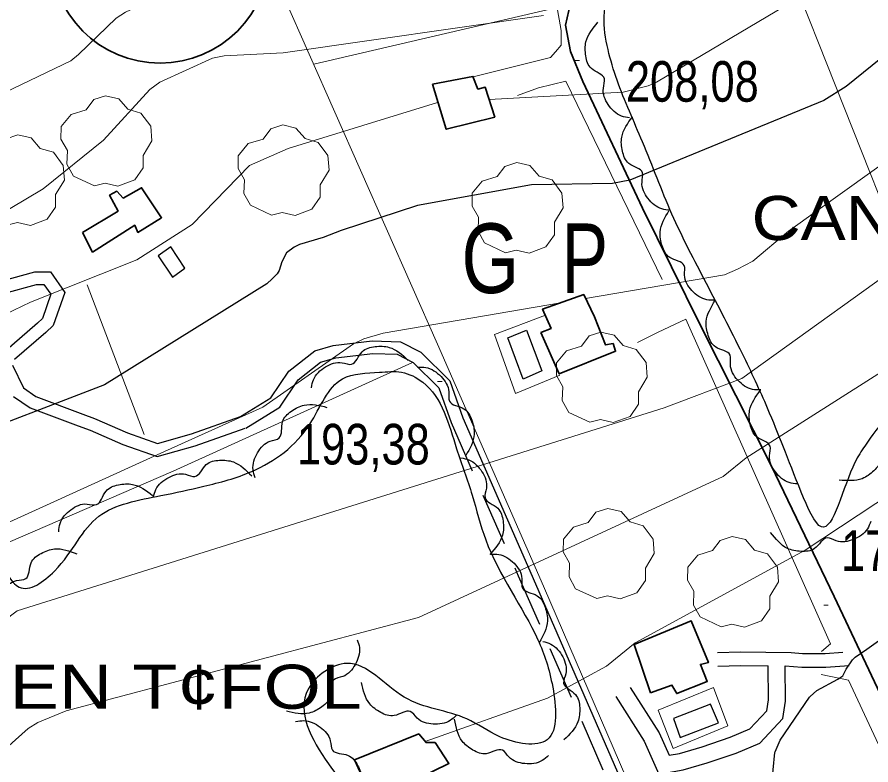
# Model space of a CAD drawing. Extents: x 483847 to 488453, y 4383581 to 4386795.
# Drawn here: x 485068.4 to 485252.4, y 4385313.2 to 4385474.4 of the extents above; entities that cross this region are included whole.
import ezdxf
from ezdxf.enums import TextEntityAlignment as Align

# ---------------------------------------------------------------- set-up
doc = ezdxf.new("R2010")
doc.units = 0
doc.header["$LTSCALE"] = 3.8
doc.linetypes.add('MEDIUM_DASHED', pattern=[4.5, 3, -1.5])
for name, color, linetype, lineweight in [('21', 7, 'Continuous', 25), ('27', 7, 'Continuous', 25), ('29', 7, 'Continuous', 13), ('38', 7, 'Continuous', 25), ('47', 7, 'Continuous', 35), ('51', 7, 'Continuous', 13), ('6', 7, 'Continuous', 35), ('7', 7, 'Continuous', 13), ('8', 7, 'Continuous', 25), ('9', 7, 'Continuous', 13)]:
    doc.layers.add(name, color=color, linetype=linetype, lineweight=lineweight)
doc.layers.add('31', color=7, linetype='Continuous')
doc.layers.add('5', color=7, linetype='Continuous')

msp = doc.modelspace()

# ---------------------------------------------------------------- linework, layer by layer
at = {"layer": '21'}
for points in [[(485098.8, 4385422.92), (485101.88, 4385418.32), (485104.57, 4385420.22), (485101.57, 4385424.87)], [(485178.15, 4385406.92), (485181.51, 4385398.11), (485177.48, 4385396.33), (485174.18, 4385405.25)], [(485211.28, 4385319.12), (485219.58, 4385322.31), (485217.81, 4385326.32), (485209.87, 4385323.23)]]:
    msp.add_lwpolyline(points, close=True, dxfattribs=at)
at = {"layer": '27'}
for points in [[(485299.82, 4385661.09), (485299.57, 4385662.67), (485294.64, 4385662.26), (485289.35, 4385654.61), (485280.21, 4385639.63), (485274.93, 4385631.94), (485268.4, 4385624.36), (485262.52, 4385617.77), (485260.31, 4385607.35), (485262.6, 4385605.35), (485273.48, 4385605.45), (485283.86, 4385606.12), (485288.68, 4385605.94), (485297.69, 4385606.01), (485307.73, 4385605.36), (485308.16, 4385598.4), (485301.92, 4385587.38), (485297.42, 4385582.21), (485286.33, 4385574.25), (485278.48, 4385567.13), (485277.89, 4385561.88), (485288.28, 4385555.36), (485288.05, 4385546.54), (485287.2, 4385540.29), (485287.59, 4385539.37), (485289.86, 4385531.35), (485293.31, 4385521.81), (485297.19, 4385508.56), (485300.77, 4385499.7), (485307.19, 4385485.75), (485313.31, 4385470.51), (485320.46, 4385455.75), (485325.62, 4385443.27), (485329.88, 4385435.24), (485331.55, 4385428.22), (485327.33, 4385421.28), (485318.2, 4385418.81), (485302.73, 4385416.83), (485290.31, 4385410.43), (485280.75, 4385407.62), (485276.69, 4385406.23), (485271.89, 4385402.9), (485261.87, 4385394.73), (485251.06, 4385381.93), (485248.95, 4385378.4), (485241.73, 4385364.5), (485237.39, 4385372.01), (485230.13, 4385390.06), (485224.7, 4385401.81), (485216.95, 4385416.96), (485209.52, 4385431.92), (485203.19, 4385447.45), (485197.7, 4385460.77), (485195.75, 4385467.38), (485194.93, 4385474.55), (485200.43, 4385487.01), (485210.67, 4385493.29), (485216.48, 4385500.54), (485216.66, 4385510.32), (485213.78, 4385515.61), (485201.98, 4385523.45), (485188.34, 4385524.69), (485179.71, 4385525), (485175.53, 4385527.17), (485167.01, 4385529.85), (485158.32, 4385525.02), (485150.05, 4385519.91), (485142.58, 4385519.6), (485127.69, 4385523.06), (485122.02, 4385531.44), (485127.14, 4385537.4), (485137.41, 4385536.78), (485149.71, 4385533.1), (485155.77, 4385534.88), (485159.76, 4385539.39), (485157.38, 4385543.53), (485170.25, 4385547.87), (485180.21, 4385553.72), (485186.2, 4385561.9), (485185.3, 4385569.26), (485178.59, 4385574.36), (485170, 4385578.4), (485148.21, 4385590.42), (485129.65, 4385601.13), (485118.26, 4385609.29), (485112.23, 4385612.98), (485102.9, 4385618.84), (485099.35, 4385621.2), (485098.35, 4385621.8), (485099.39, 4385628.01), (485103.9, 4385633.91)], [(485138.09, 4385491.7), (485117.52, 4385494.92), (485086.01, 4385503.28), (485081.51, 4385513.57), (485077.65, 4385527.72), (485084.73, 4385543.16), (485084.73, 4385555.38), (485066.08, 4385566.96), (485045.5, 4385568.25), (485042.29, 4385563.1), (485044.86, 4385545.73), (485048.08, 4385539.3), (485038.43, 4385530.3), (485026.22, 4385523.86), (485021.07, 4385512.28), (485022.36, 4385491.06), (485024.29, 4385447.96), (485003.07, 4385438.95), (484987.64, 4385455.68), (484988.92, 4385488.48), (484976.71, 4385515.5), (484956.13, 4385517.43), (484943.27, 4385480.76), (484939.42, 4385462.75), (484925.91, 4385453.1), (484916.27, 4385460.18), (484918.84, 4385487.84), (484918.2, 4385505.85), (484902.77, 4385501.35), (484880.26, 4385476.26), (484861.62, 4385445.39), (484883.48, 4385433.16), (484904.7, 4385434.45), (484917.56, 4385425.44), (484886.69, 4385394.57), (484833.97, 4385350.18), (484770.96, 4385312.88), (484729.17, 4385266.56), (484722.1, 4385262.06)], [(485200.39, 4385452.64), (485198.66, 4385453.01), (485195.79, 4385455.5), (485194.74, 4385459.03), (485194.98, 4385461.07), (485192.18, 4385463.26), (485190.96, 4385465.99), (485190.99, 4385469.01), (485193.58, 4385473.24)], [(485209.12, 4385432.74), (485207.36, 4385433), (485204.34, 4385435.3), (485203.07, 4385438.76), (485203.18, 4385440.81), (485200.24, 4385442.82), (485198.86, 4385445.47), (485198.7, 4385448.49), (485201.02, 4385452.87)], [(485218.82, 4385413.33), (485217.05, 4385413.43), (485213.83, 4385415.43), (485212.24, 4385418.76), (485212.16, 4385420.82), (485209.05, 4385422.54), (485207.42, 4385425.04), (485206.98, 4385428.03), (485208.87, 4385432.62)], [(485228.69, 4385394), (485226.91, 4385394.11), (485223.7, 4385396.13), (485222.12, 4385399.47), (485222.05, 4385401.52), (485218.95, 4385403.26), (485217.34, 4385405.77), (485216.91, 4385408.76), (485218.83, 4385413.33)], [(485131.82, 4385394.49), (485132.26, 4385396.21), (485134.87, 4385398.97), (485138.45, 4385399.87), (485140.47, 4385399.54), (485142.78, 4385402.25), (485145.56, 4385403.35), (485148.57, 4385403.19), (485152.69, 4385400.42)], [(485154.72, 4385398.91), (485156.49, 4385398.85), (485159.76, 4385396.92), (485161.43, 4385393.63), (485161.56, 4385391.58), (485164.71, 4385389.93), (485166.4, 4385387.47), (485166.91, 4385384.49), (485165.11, 4385379.86)], [(485052.44, 4385364.8), (485048.92, 4385362.19), (485040.02, 4385358.72), (485024.72, 4385354.86), (485017.53, 4385351.95), (485003.29, 4385349.24), (484982.72, 4385342.51), (484974.56, 4385332.02), (484981.15, 4385319.05), (484982.31, 4385313.35), (484982.65, 4385294.37), (484983.39, 4385269.53), (484987.68, 4385251.41), (484996.81, 4385238.57), (485031.48, 4385237.2), (485037.8, 4385239.34), (485054.61, 4385248.35), (485064.38, 4385252.89), (485078.44, 4385258.07), (485096.56, 4385262.47), (485096.84, 4385262.77), (485103.74, 4385262.86), (485111.59, 4385265.05), (485112.39, 4385270.45), (485114.5, 4385279.23), (485120.51, 4385283.33), (485139.84, 4385291), (485153.97, 4385297.17), (485158.64, 4385300.35), (485154.47, 4385304.25), (485147.71, 4385304.01), (485135.53, 4385313.41), (485131.15, 4385329.54), (485139.45, 4385335.08), (485151.84, 4385327.8), (485165.34, 4385323.12), (485172.43, 4385319.28), (485182.63, 4385318.65), (485183.82, 4385329.99), (485180.64, 4385340.15), (485169.39, 4385361.72), (485166.47, 4385371.34), (485163.13, 4385381.35), (485155.81, 4385395.69), (485151.26, 4385397.82), (485146.5, 4385397.81), (485138.56, 4385396.41), (485131.49, 4385386.65), (485118.99, 4385376.45), (485108.62, 4385373.24), (485099.38, 4385371.24), (485086.02, 4385366.81), (485076.47, 4385354.99), (485068.85, 4385351.52), (485066.46, 4385354.04), (485060, 4385363.04), (485052.44, 4385364.8)], [(485236.57, 4385373.76), (485234.81, 4385374.04), (485231.81, 4385376.36), (485230.56, 4385379.83), (485230.68, 4385381.88), (485227.76, 4385383.91), (485226.39, 4385386.56), (485226.26, 4385389.58), (485228.6, 4385393.95)], [(485258.54, 4385391.99), (485259.23, 4385390.35), (485258.84, 4385386.58), (485256.55, 4385383.68), (485254.74, 4385382.71), (485254.56, 4385379.16), (485253.02, 4385376.6), (485250.53, 4385374.89), (485245.58, 4385374.58)], [(485119.68, 4385375.09), (485119.25, 4385376.81), (485120.23, 4385380.48), (485122.94, 4385382.98), (485124.88, 4385383.66), (485125.61, 4385387.14), (485127.53, 4385389.43), (485130.26, 4385390.73), (485135.19, 4385390.26)], [(485097.75, 4385370.88), (485098.31, 4385372.56), (485101.08, 4385375.15), (485104.71, 4385375.83), (485106.71, 4385375.37), (485109.18, 4385377.93), (485112.02, 4385378.85), (485115.02, 4385378.5), (485118.96, 4385375.48)], [(485164.06, 4385379.36), (485165.78, 4385378.94), (485168.58, 4385376.38), (485169.54, 4385372.81), (485169.24, 4385370.78), (485171.98, 4385368.51), (485173.12, 4385365.75), (485173.01, 4385362.73), (485170.3, 4385358.58)], [(485077.38, 4385363.46), (485077.67, 4385365.22), (485080, 4385368.2), (485083.49, 4385369.43), (485085.53, 4385369.29), (485087.58, 4385372.2), (485090.24, 4385373.55), (485093.27, 4385373.67), (485097.62, 4385371.29)], [(485252.36, 4385365.69), (485251.64, 4385364.07), (485248.61, 4385361.78), (485244.93, 4385361.48), (485242.99, 4385362.14), (485240.27, 4385359.85), (485237.35, 4385359.22), (485234.4, 4385359.87), (485230.79, 4385363.28)], [(485064.1, 4385345.48), (485063.88, 4385347.24), (485065.28, 4385350.76), (485068.28, 4385352.93), (485070.28, 4385353.37), (485071.43, 4385356.74), (485073.6, 4385358.79), (485076.46, 4385359.75), (485081.31, 4385358.7)], [(485170.44, 4385358.61), (485172.21, 4385358.56), (485175.49, 4385356.65), (485177.18, 4385353.36), (485177.31, 4385351.31), (485180.47, 4385349.68), (485182.17, 4385347.22), (485182.7, 4385344.25), (485180.93, 4385339.61)], [(485141.71, 4385340.19), (485142.17, 4385338.48), (485141.25, 4385334.8), (485138.57, 4385332.25), (485136.64, 4385331.54), (485135.96, 4385328.06), (485134.08, 4385325.74), (485131.37, 4385324.39), (485126.43, 4385324.79)], [(485181.73, 4385339.83), (485183.41, 4385339.26), (485185.99, 4385336.48), (485186.65, 4385332.85), (485186.18, 4385330.85), (485188.73, 4385328.36), (485189.64, 4385325.52), (485189.27, 4385322.52), (485186.23, 4385318.6)], [(485163.11, 4385323.93), (485161.76, 4385322.78), (485158.05, 4385322), (485154.6, 4385323.3), (485153.12, 4385324.73), (485149.68, 4385323.83), (485146.77, 4385324.51), (485144.39, 4385326.36), (485142.59, 4385330.99)], [(485182.93, 4385315.24), (485181.55, 4385314.13), (485177.81, 4385313.49), (485174.4, 4385314.92), (485172.98, 4385316.4), (485169.51, 4385315.63), (485166.63, 4385316.41), (485164.31, 4385318.36), (485162.69, 4385323.04)], [(485128.43, 4385322.53), (485130.19, 4385322.76), (485133.72, 4385321.38), (485135.9, 4385318.4), (485136.36, 4385316.4), (485139.73, 4385315.27), (485141.79, 4385313.11), (485142.78, 4385310.26), (485141.75, 4385305.4)]]:
    msp.add_spline(points, degree=3, dxfattribs=at)
at = {"layer": '29'}
for points in [[(485085.09, 4385437.99), (485080.55, 4385440.11), (485079.14, 4385442.65), (485079.24, 4385445.63), (485077.87, 4385448.04), (485077.91, 4385450.79), (485080.07, 4385453.39), (485083.26, 4385454.39), (485084.91, 4385456.58), (485087.48, 4385457.41), (485090.34, 4385456.76), (485092.29, 4385454.49), (485095.1, 4385453.67), (485097.23, 4385450.82), (485097.47, 4385447.69), (485095.59, 4385444.54), (485095.59, 4385441.86), (485093.77, 4385439.25), (485090.15, 4385437.91), (485087.38, 4385438.54)], [(485123.25, 4385431.68), (485118.71, 4385433.8), (485117.3, 4385436.34), (485117.4, 4385439.32), (485116.03, 4385441.73), (485116.07, 4385444.48), (485118.23, 4385447.08), (485121.42, 4385448.08), (485123.07, 4385450.27), (485125.64, 4385451.1), (485128.5, 4385450.45), (485130.45, 4385448.18), (485133.26, 4385447.36), (485135.39, 4385444.51), (485135.63, 4385441.38), (485133.75, 4385438.23), (485133.75, 4385435.55), (485131.93, 4385432.94), (485128.31, 4385431.6), (485125.54, 4385432.23)], [(485066.21, 4385429.54), (485061.67, 4385431.66), (485060.26, 4385434.2), (485060.36, 4385437.18), (485058.99, 4385439.59), (485059.03, 4385442.34), (485061.19, 4385444.94), (485064.38, 4385445.94), (485066.03, 4385448.13), (485068.6, 4385448.96), (485071.46, 4385448.31), (485073.41, 4385446.04), (485076.22, 4385445.22), (485078.35, 4385442.37), (485078.59, 4385439.24), (485076.71, 4385436.09), (485076.71, 4385433.41), (485074.89, 4385430.8), (485071.27, 4385429.46), (485068.5, 4385430.09)], [(485173.68, 4385423.58), (485169.14, 4385425.7), (485167.73, 4385428.24), (485167.83, 4385431.22), (485166.46, 4385433.63), (485166.5, 4385436.38), (485168.66, 4385438.98), (485171.85, 4385439.98), (485173.5, 4385442.17), (485176.07, 4385443), (485178.93, 4385442.35), (485180.88, 4385440.08), (485183.69, 4385439.26), (485185.82, 4385436.41), (485186.06, 4385433.28), (485184.18, 4385430.13), (485184.18, 4385427.45), (485182.36, 4385424.84), (485178.74, 4385423.5), (485175.97, 4385424.13)], [(485191.83, 4385387.06), (485187.29, 4385389.18), (485185.88, 4385391.72), (485185.98, 4385394.7), (485184.61, 4385397.11), (485184.65, 4385399.86), (485186.81, 4385402.46), (485190, 4385403.46), (485191.65, 4385405.65), (485194.22, 4385406.48), (485197.08, 4385405.83), (485199.03, 4385403.56), (485201.84, 4385402.74), (485203.97, 4385399.89), (485204.21, 4385396.76), (485202.33, 4385393.61), (485202.33, 4385390.93), (485200.51, 4385388.32), (485196.89, 4385386.98), (485194.12, 4385387.61)], [(485193.31, 4385349.06), (485188.77, 4385351.18), (485187.36, 4385353.72), (485187.46, 4385356.7), (485186.09, 4385359.11), (485186.13, 4385361.86), (485188.29, 4385364.46), (485191.48, 4385365.46), (485193.13, 4385367.65), (485195.7, 4385368.48), (485198.56, 4385367.83), (485200.51, 4385365.56), (485203.32, 4385364.74), (485205.45, 4385361.89), (485205.69, 4385358.76), (485203.81, 4385355.61), (485203.81, 4385352.93), (485201.99, 4385350.32), (485198.37, 4385348.98), (485195.6, 4385349.61)], [(485220.11, 4385342.99), (485215.57, 4385345.11), (485214.16, 4385347.65), (485214.26, 4385350.63), (485212.89, 4385353.04), (485212.93, 4385355.79), (485215.09, 4385358.39), (485218.28, 4385359.39), (485219.93, 4385361.58), (485222.5, 4385362.41), (485225.36, 4385361.76), (485227.31, 4385359.49), (485230.12, 4385358.67), (485232.25, 4385355.82), (485232.49, 4385352.69), (485230.61, 4385349.54), (485230.61, 4385346.86), (485228.79, 4385344.25), (485225.17, 4385342.91), (485222.4, 4385343.54)]]:
    msp.add_lwpolyline(points, close=True, dxfattribs=at)
at = {"layer": '38'}
for points in [[(485065.19, 4385417.49), (485072.25, 4385419.43), (485075.62, 4385419.44), (485078.69, 4385415.03), (485076.2, 4385407.88), (485074.63, 4385406.38), (485067.86, 4385400.55)], [(485067.39, 4385399.36), (485069.79, 4385394.43), (485072.48, 4385392.57), (485082.54, 4385388.78), (485085.12, 4385387.84), (485092.19, 4385384.78), (485098.68, 4385382.49), (485105.97, 4385384.57), (485116.53, 4385388.26), (485123.1, 4385392.33), (485126.98, 4385398.05), (485132.55, 4385402.45), (485136.54, 4385403.6), (485144.94, 4385404.58), (485151.01, 4385404.41), (485155.4, 4385402.14), (485161.67, 4385395.96), (485164.46, 4385388.01), (485178.88, 4385355.05), (485199.04, 4385308.83)], [(485219.31, 4385337.44), (485224.28, 4385337.58), (485235.23, 4385337.44), (485237.65, 4385337.25), (485242.56, 4385337.24), (485246.36, 4385337.51)], [(485197.46, 4385327.96), (485203.56, 4385318.36), (485206.72, 4385311.25), (485211.95, 4385312.14), (485217.14, 4385313.66), (485223.37, 4385315.76), (485228.43, 4385317.92), (485233.42, 4385323.18), (485234.01, 4385326.96), (485233.89, 4385334.57)], [(485200.54, 4385329.92), (485206.79, 4385320.09), (485208.9, 4385315.33), (485211.13, 4385315.7), (485216.04, 4385317.14), (485222.07, 4385319.17), (485226.3, 4385320.98), (485229.99, 4385324.87), (485230.35, 4385327.21), (485230.24, 4385334.54)], [(485219.39, 4385334.48), (485224.3, 4385334.62), (485230.24, 4385334.54)], [(485233.89, 4385334.57), (485237.53, 4385334.29), (485242.66, 4385334.28), (485247.71, 4385334.64)]]:
    msp.add_lwpolyline(points, dxfattribs=at)
at = {"layer": '38', "linetype": 'MEDIUM_DASHED'}
for points in [[(485065.77, 4385414.84), (485072.62, 4385416.72), (485074.2, 4385416.72), (485075.68, 4385414.62), (485073.85, 4385409.39), (485072.8, 4385408.39), (485065.59, 4385402.17)], [(485067.66, 4385392.6), (485071.21, 4385390.15), (485081.6, 4385386.24), (485084.12, 4385385.32), (485091.2, 4385382.25), (485098.59, 4385379.65), (485106.79, 4385381.98), (485117.7, 4385385.79), (485125.02, 4385390.33), (485128.99, 4385396.18), (485133.82, 4385399.99), (485137.08, 4385400.94), (485145.06, 4385401.86), (485150.31, 4385401.71), (485153.79, 4385399.92), (485159.32, 4385394.47), (485161.93, 4385387.02), (485176.4, 4385353.96), (485196.56, 4385307.73)]]:
    msp.add_lwpolyline(points, dxfattribs=at)
at = {"layer": '47'}
for points in [[(485157.91, 4385459.88), (485160.87, 4385450.17), (485171.35, 4385452.79), (485169.29, 4385459.24), (485167.71, 4385458.83), (485166.62, 4385461.56)], [(485082.53, 4385427.94), (485084.69, 4385423.7), (485093.76, 4385429.51), (485094.46, 4385427.94), (485099.56, 4385431.12), (485095.24, 4385437.59), (485091.29, 4385435.36), (485089.9, 4385436.83), (485088.33, 4385435.98), (485090.17, 4385432.56)], [(485181.27, 4385406.37), (485185.25, 4385397.47), (485197.39, 4385402.36), (485196.83, 4385404), (485195.21, 4385403.7), (485192.81, 4385409.78), (485190.5, 4385414.54), (485181.65, 4385411.45), (485183.49, 4385407.27)], [(485204.89, 4385328.76), (485201.35, 4385339.15), (485213.69, 4385344.25), (485217.37, 4385335.26), (485215.64, 4385334.88), (485217.12, 4385331.16), (485210.57, 4385328.57), (485209.5, 4385330.43)], [(485141.14, 4385314.33), (485145.12, 4385305.57), (485161.46, 4385313.55), (485158.47, 4385318.05), (485156.53, 4385318.03), (485154.97, 4385319.9)]]:
    msp.add_lwpolyline(points, close=True, dxfattribs=at)
at = {"layer": '51'}
for p, q in [((485184.77, 4385476.42), (485132.37, 4385464.18)), ((485095.77, 4385384.39), (485083.48, 4385416.69))]:
    msp.add_line(p, q, dxfattribs=at)
for points in [[(485339.37, 4385421.12), (485279.8, 4385375.88), (485259.62, 4385422.12), (485233.6, 4385487.71), (485220.71, 4385521.12)], [(485179.99, 4385489.18), (485180.55, 4385483.65), (485183.72, 4385481.9), (485184.64, 4385477.14), (485185.67, 4385471.49), (485185.65, 4385468.27), (485184.4, 4385466.9), (485183.33, 4385465.68), (485166.67, 4385461.46)], [(485285.53, 4385247.86), (485313.01, 4385192.5), (485313.42, 4385190.87), (485268.44, 4385152.71), (485257.99, 4385177.32), (485238.37, 4385220.27), (485217.56, 4385269.02), (485181.87, 4385351.76), (485159, 4385403.87), (485125.85, 4385478.91)], [(485207.45, 4385417.8), (485186.67, 4385460.58), (485180.78, 4385459.08), (485176.23, 4385457.47)], [(485185.34, 4385397.22), (485175.82, 4385393.26), (485171.26, 4385405.95), (485182.25, 4385410.09)], [(485241.72, 4385337.66), (485243.71, 4385339.31), (485212.54, 4385409.27), (485206.57, 4385406.45), (485202.08, 4385404.26)], [(485153.65, 4385399.89), (485102.04, 4385376.52), (485031.36, 4385345.95)], [(485280.64, 4385252.83), (485282.73, 4385255.99), (485247.58, 4385331.44), (485241.69, 4385332.71)]]:
    msp.add_lwpolyline(points, dxfattribs=at)
msp.add_lwpolyline([(485218.51, 4385329.88), (485221.53, 4385321.65), (485209.79, 4385316.72), (485206.56, 4385325)], close=True, dxfattribs=at)
at = {"layer": '6'}
msp.add_lwpolyline([(485255.01, 4385327.15), (485244.49, 4385349.47), (485230.92, 4385377.71), (485215.65, 4385407.92), (485203.16, 4385433.2), (485190.33, 4385460.5), (485187.63, 4385466.91), (485186.62, 4385472.64), (485187.63, 4385477.36)], dxfattribs=at)
msp.add_circle((485099.22, 4385487.99), 23.55, dxfattribs=at)
at = {"layer": '7'}
for p, q in [((485188.59, 4385464.98), (485189.59, 4385464.98)), ((485158.98, 4385395.83), (485159.98, 4385395.83)), ((485242.22, 4385347.62), (485243.22, 4385347.62))]:
    msp.add_line(p, q, dxfattribs=at)
at = {"layer": '8'}
for points in [[(485261.67, 4385471.15), (485247.08, 4385459.38), (485242.22, 4385456.39), (485200.45, 4385439.21), (485196.72, 4385438.49), (485179.29, 4385438.22), (485154.72, 4385433.77), (485138.23, 4385428.4), (485134.34, 4385426.84), (485129.23, 4385425.36), (485128.13, 4385424.78), (485126.48, 4385423.52), (485125.43, 4385421.58), (485124.9, 4385419.73), (485124.42, 4385419.03), (485123.38, 4385417.93), (485122.22, 4385416.91), (485087.22, 4385395.08), (485053.89, 4385382.33), (484777.81, 4385260.43)], [(485229.41, 4385304.35), (485230.48, 4385306.55), (485230.95, 4385308.33), (485231.36, 4385312.16), (485231.7, 4385315.91), (485231.74, 4385316.06), (485232.81, 4385318.56), (485239.18, 4385327.79), (485239.3, 4385327.94), (485240.77, 4385329.25), (485245.24, 4385331.67), (485246.36, 4385332.42), (485246.37, 4385332.43), (485246.39, 4385332.57), (485247.04, 4385333.85), (485248.43, 4385335.82), (485249.03, 4385336.42), (485251.55, 4385338.13), (485280.38, 4385358.8)]]:
    msp.add_lwpolyline(points, dxfattribs=at)
at = {"layer": '9'}
msp.add_line((485185.52, 4385412.8), (485185.51, 4385412.8), dxfattribs=at)
for points in [[(485170.13, 4385456.6), (485199.02, 4385458.19), (485204.41, 4385459.52), (485206.16, 4385460.3), (485265.8, 4385495.74)], [(484674.5, 4385265.7), (484710.01, 4385288.04), (484750.8, 4385303.05), (484860.33, 4385359.54), (485079.99, 4385464.95), (485081.67, 4385466.28), (485089.78, 4385474.12), (485091.78, 4385475.4), (485099.75, 4385479.19), (485102.45, 4385479.84), (485151.07, 4385485.69)], [(484938.49, 4385385.51), (485008.27, 4385406.46), (485053.35, 4385425.05), (485074.05, 4385437.35), (485087.01, 4385447.85), (485096.98, 4385458.74), (485099.16, 4385460.36), (485110.52, 4385465.49), (485113.06, 4385465.99), (485125.73, 4385466.65), (485181.83, 4385474.67)], [(485316.76, 4385474.04), (485287.99, 4385466.4), (485234.63, 4385428.2), (485226.93, 4385421.78), (485223.67, 4385420.02), (485220.84, 4385418.84), (485190.9, 4385413.72)], [(485382.47, 4385473.16), (485349.11, 4385464.77), (485305.06, 4385449), (485265.15, 4385425.62), (485224.59, 4385396.48), (485207.83, 4385390.17), (485068.44, 4385346.38), (485066.97, 4385345.31), (485066.31, 4385344.71), (485062.35, 4385340.08), (485054.14, 4385332.87), (484883.38, 4385253.17)], [(484909.29, 4385347.22), (485026.34, 4385391.41), (485071.27, 4385412.94), (485094.19, 4385422.07), (485106.17, 4385429.64), (485118.51, 4385442.39), (485126.82, 4385446.07), (485158.97, 4385455.98), (485159.1, 4385455.99)], [(485484.6, 4385455.96), (485468.17, 4385442.31), (485459.78, 4385437), (485451.15, 4385433.42), (485445.9, 4385432.14), (485435.56, 4385431.09), (485400.99, 4385431.46), (485394.85, 4385431.01), (485385.26, 4385431.78), (485348.16, 4385421.11), (485287.91, 4385392.32), (485238.24, 4385359.46), (485201.58, 4385339.51), (485195.44, 4385334.48), (485182.69, 4385327.58), (485156.35, 4385318.24)], [(484767.17, 4385173.58), (485050.82, 4385305.37), (485057.03, 4385308.78), (485070.82, 4385321.07), (485072.86, 4385322.34), (485078.99, 4385324.87), (485154.91, 4385344.97), (485220.59, 4385375.39), (485225.52, 4385379.41), (485298.21, 4385425.54)], [(485185.51, 4385412.8), (485147.26, 4385406.25), (485143.11, 4385404.99), (485140.9, 4385403.98), (485121.36, 4385390.31), (485097.98, 4385379.73), (484757.4, 4385224.8)]]:
    msp.add_lwpolyline(points, dxfattribs=at)

# ---------------------------------------------------------------- texts
at = {"layer": '31'}
for s, width, p in [('G', 0.8, (485170.4, 4385414.89)), ('P', 0.75, (485190.74, 4385414.88))]:
    msp.add_text(s, height=15, dxfattribs=dict(at, width=width)).set_placement(p, align=Align.CENTER)
at = {"layer": '5'}
for s, width, p in [('CAN QUELEU', 1.15, (485226.69, 4385426.31)), ("PINARET D'EN T¢FOL", 1.25, (484979.07, 4385325.31))]:
    msp.add_text(s, height=9.5, dxfattribs=dict(at, width=width)).set_placement(p)
at = {"layer": '7', "width": 0.8}
for s, p in [('208,08', (485199.6, 4385456.12)), ('193,38', (485128.71, 4385377.95)), ('177,93', (485245.97, 4385355.02))]:
    msp.add_text(s, height=8.75, dxfattribs=at).set_placement(p)

doc.saveas('drawing.dxf')
